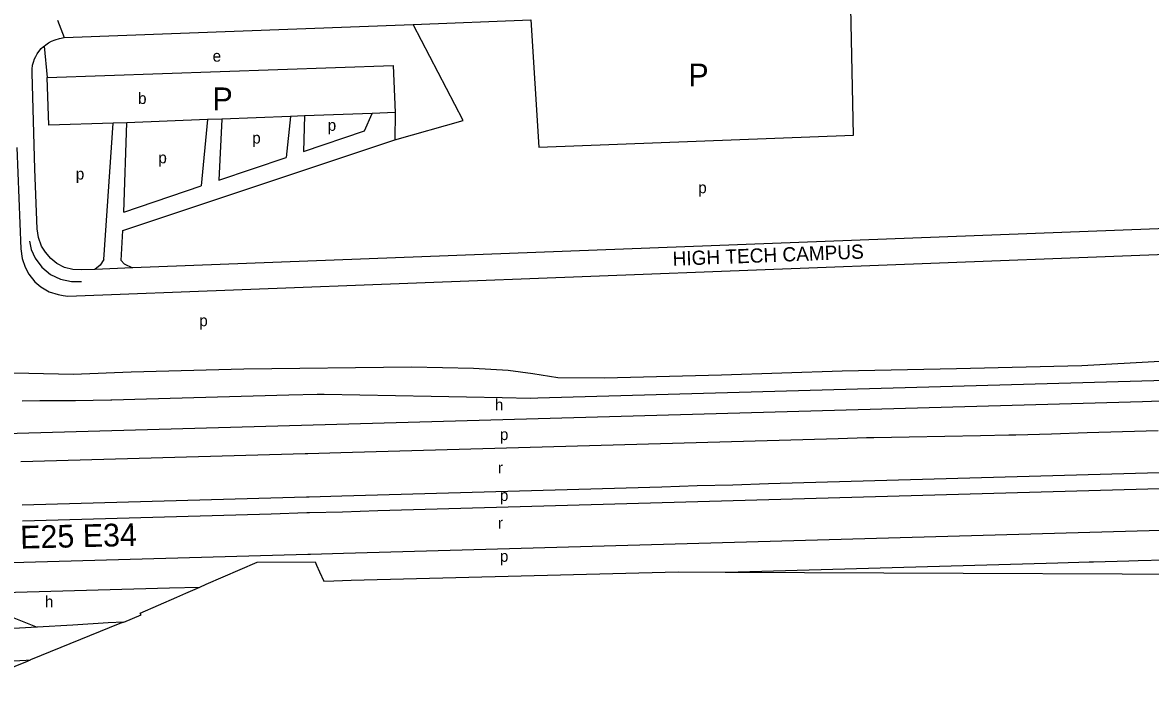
# Model space of a CAD drawing. Extents: x 158358 to 160383, y 379531 to 380764.
# Drawn here: x 159510.8 to 159907.3, y 379530.7 to 379764 of the extents above; entities that cross this region are included whole.
import ezdxf

# ---------------------------------------------------------------- set-up
doc = ezdxf.new("R2010")
doc.units = 0
for name, color, linetype in [('BLT_Basislijn', 7, 'Continuous'), ('BLT_Bebouwing', 7, 'Continuous'), ('BLT_Centroide', 7, 'Continuous'), ('BLT_Gemeentegrens', 7, 'Continuous'), ('BLT_Straatnaam', 7, 'Continuous'), ('BLT_Straatnaam_hoofdweg', 7, 'Continuous'), ('BLT_Tekst_parkeren', 7, 'Continuous'), ('BLT_Vlakafsluiter', 7, 'Continuous')]:
    doc.layers.add(name, color=color, linetype=linetype)

msp = doc.modelspace()

# ---------------------------------------------------------------- linework, layer by layer
at = {"layer": 'BLT_Basislijn'}
for p, q in [((159525.38, 379758.64), (159648.05, 379763.32)), ((159648.05, 379763.32), (159689.44, 379764.9)), ((159665.69, 379729.54), (159648.05, 379763.32)), ((159518.33, 379755.67), (159519.37, 379744.66)), ((159575.83, 379729.79), (159573.61, 379706.46)), ((159580.82, 379729.98), (159579.81, 379708.55)), ((159604.93, 379730.89), (159603.4, 379716.5)), ((159609.92, 379731.08), (159609.58, 379718.58)), ((159641.7, 379732.3), (159641.68, 379722.65)), ((159539.39, 379680.61), (159542.61, 379728.52)), ((159546.35, 379697.27), (159547.42, 379728.71)), ((159641.68, 379722.65), (159665.69, 379729.54)), ((159545.98, 379690.82), (159641.68, 379722.65)), ((159545.38, 379680.27), (159545.98, 379690.82)), ((159951.34, 379692.96), (159549.4, 379677.61))]:
    msp.add_line(p, q, dxfattribs=at)
for points in [[(159689.44, 379764.9), (159692.26, 379720.15), (159802.92, 379724.35), (159801.98, 379769.17)], [(159518.33, 379755.67), (159518.89, 379756.11), (159519.88, 379756.78), (159520.99, 379757.38), (159522.24, 379757.87), (159523.78, 379758.31), (159525.38, 379758.64)], [(159515.08, 379712.39), (159514.08, 379746.22), (159514.1, 379747.6), (159514.31, 379748.99), (159514.56, 379750), (159514.97, 379751.16), (159515.4, 379752.05), (159515.89, 379752.94), (159516.5, 379753.8), (159517.33, 379754.78), (159518.13, 379755.51), (159518.33, 379755.67)], [(159508.74, 379720.04), (159510.15, 379684.35), (159510.58, 379680.95), (159511.63, 379677.83), (159512.96, 379675.4), (159515.12, 379672.76), (159517.23, 379670.91), (159520.09, 379669.22), (159523.31, 379668.22), (159525, 379667.9), (159526.69, 379667.74), (160139.53, 379691.14), (160142.9, 379691.52), (160144.79, 379692.1), (160146.54, 379692.75), (160148.23, 379693.53), (160149.78, 379694.5), (160152.48, 379696.8), (160183.67, 379730.79)], [(159609.58, 379718.58), (159631, 379725.8), (159633.73, 379731.99)], [(159579.81, 379708.55), (159603.4, 379716.5)], [(159536.15, 379677.11), (159531.45, 379676.93), (159528.45, 379677.04), (159525.55, 379677.78), (159522.82, 379679.2), (159520.68, 379680.91), (159518.78, 379683.13), (159517.47, 379685.3), (159516.33, 379688.31), (159515.88, 379691.34), (159515.08, 379712.39)], [(159546.35, 379697.27), (159573.61, 379706.46)], [(159513.24, 379687.01), (159513.84, 379684.12), (159515.24, 379681.01), (159517.59, 379677.89), (159520.57, 379675.36), (159524.11, 379673.71), (159527.92, 379672.86), (159531.48, 379672.9)], [(159539.39, 379680.61), (159538.08, 379678.63), (159536.15, 379677.11)], [(159545.38, 379680.27), (159546.48, 379679.06), (159549.4, 379677.61)], [(159549.4, 379677.61), (159536.15, 379677.11)], [(159955.34, 379648.64), (159936.38, 379646.49), (159910.66, 379644.68), (159883.14, 379643.15), (159839.13, 379642.16), (159798.91, 379641.34), (159756.54, 379639.86), (159715.31, 379638.82), (159698.99, 379638.99), (159690.12, 379640.38), (159681.45, 379641.51), (159669.3, 379642.26), (159647.45, 379642.73), (159588.55, 379641.96), (159548.99, 379640.97), (159528.55, 379640.14), (159502.38, 379640.72)], [(159916.8, 379638.17), (159904.3, 379637.81), (159891.81, 379637.46), (159879.31, 379637.1), (159866.82, 379636.75), (159854.32, 379636.39), (159841.83, 379636.04), (159829.33, 379635.68), (159816.84, 379635.33), (159804.34, 379634.97), (159791.85, 379634.62), (159779.35, 379634.26), (159766.86, 379633.91), (159754.36, 379633.55), (159741.87, 379633.2), (159729.37, 379632.84), (159716.88, 379632.49), (159704.38, 379632.13), (159691.89, 379631.78), (159689.39, 379631.71), (159679.38, 379631.9), (159666.87, 379632.13), (159654.36, 379632.37), (159641.85, 379632.61), (159629.33, 379632.84), (159616.82, 379633.08), (159614.32, 379633.13), (159604.32, 379632.84), (159591.83, 379632.49), (159579.33, 379632.14), (159566.84, 379631.78), (159554.34, 379631.43), (159542.16, 379631.08), (159541.85, 379631.07), (159535.6, 379630.97), (159529.35, 379630.9), (159523.11, 379630.85), (159516.86, 379630.82), (159510.61, 379630.77)], [(159917, 379630.92), (159904.51, 379630.56), (159892.01, 379630.21), (159879.52, 379629.85), (159867.02, 379629.5), (159854.53, 379629.14), (159842.03, 379628.79), (159829.54, 379628.43), (159817.04, 379628.08), (159804.55, 379627.73), (159792.05, 379627.37), (159779.56, 379627.02), (159767.06, 379626.66), (159754.57, 379626.31), (159742.07, 379625.95), (159729.58, 379625.6), (159717.08, 379625.24), (159704.59, 379624.89), (159692.09, 379624.53), (159679.6, 379624.18), (159667.1, 379623.82), (159654.61, 379623.47), (159642.11, 379623.11), (159629.62, 379622.76), (159617.13, 379622.4), (159604.63, 379622.05), (159592.14, 379621.69), (159579.64, 379621.34), (159567.15, 379620.98), (159554.65, 379620.63), (159542.16, 379620.28), (159529.66, 379619.92), (159517.17, 379619.57), (159504.67, 379619.21)], [(159510.14, 379609.46), (159522.64, 379609.82), (159535.13, 379610.17), (159547.63, 379610.53), (159560.12, 379610.88), (159572.62, 379611.24), (159585.11, 379611.59), (159597.61, 379611.95), (159610.1, 379612.3), (159610.24, 379612.3), (159611.04, 379612.33), (159622.6, 379612.66), (159635.09, 379613.01), (159647.59, 379613.36), (159660.08, 379613.72), (159672.58, 379614.07), (159685.07, 379614.43), (159697.57, 379614.78), (159710.06, 379615.14), (159722.56, 379615.49), (159735.05, 379615.85), (159747.55, 379616.2), (159760.04, 379616.56), (159772.54, 379616.91), (159785.03, 379617.27), (159797.53, 379617.62), (159807.52, 379617.91), (159810.02, 379617.95), (159822.52, 379618.2), (159835.02, 379618.44), (159847.52, 379618.68), (159857.52, 379618.87), (159860.02, 379618.95), (159872.51, 379619.3), (159885.01, 379619.66), (159897.5, 379620.01), (159910, 379620.37)], [(159510.58, 379594.27), (159523.07, 379594.62), (159535.57, 379594.98), (159548.06, 379595.33), (159560.56, 379595.69), (159573.05, 379596.04), (159585.55, 379596.4), (159598.04, 379596.75), (159610.54, 379597.11), (159610.67, 379597.11), (159611.47, 379597.13), (159623.03, 379597.46), (159635.53, 379597.82), (159648.02, 379598.17), (159660.52, 379598.53), (159673.01, 379598.88), (159685.51, 379599.24), (159698, 379599.59), (159710.5, 379599.94), (159722.99, 379600.3), (159735.49, 379600.65), (159747.98, 379601.01), (159760.48, 379601.36), (159772.97, 379601.72), (159785.47, 379602.07), (159797.96, 379602.43), (159810.45, 379602.78), (159822.95, 379603.14), (159835.44, 379603.49), (159847.94, 379603.85), (159860.43, 379604.2), (159872.93, 379604.56), (159885.42, 379604.91), (159897.92, 379605.27), (159910.41, 379605.62)], [(159510.73, 379588.67), (159523.23, 379589.03), (159535.72, 379589.38), (159548.22, 379589.73), (159560.71, 379590.09), (159573.21, 379590.44), (159585.7, 379590.8), (159598.2, 379591.15), (159610.69, 379591.51), (159610.83, 379591.51), (159611.63, 379591.54), (159623.19, 379591.86), (159635.68, 379592.22), (159648.18, 379592.57), (159660.67, 379592.93), (159673.17, 379593.28), (159685.66, 379593.64), (159698.16, 379593.99), (159710.65, 379594.35), (159723.15, 379594.7), (159735.64, 379595.06), (159748.14, 379595.41), (159760.63, 379595.77), (159773.13, 379596.12), (159785.62, 379596.48), (159798.12, 379596.83), (159810.61, 379597.19), (159823.11, 379597.54), (159835.6, 379597.89), (159848.1, 379598.25), (159860.59, 379598.6), (159873.09, 379598.96), (159885.58, 379599.31), (159898.08, 379599.67), (159910.57, 379600.02)], [(159910.99, 379585.28), (159898.5, 379584.92), (159886, 379584.57), (159873.51, 379584.21), (159861.01, 379583.86), (159848.52, 379583.51), (159836.02, 379583.15), (159823.53, 379582.8), (159811.03, 379582.44), (159798.54, 379582.09), (159786.04, 379581.73), (159773.55, 379581.38), (159761.05, 379581.02), (159748.56, 379580.67), (159736.06, 379580.31), (159723.57, 379579.96), (159711.07, 379579.6), (159698.58, 379579.25), (159686.08, 379578.89), (159673.59, 379578.54), (159661.09, 379578.18), (159648.6, 379577.83), (159636.1, 379577.47), (159623.61, 379577.12), (159612.05, 379576.79), (159611.25, 379576.77), (159611.11, 379576.76), (159598.62, 379576.41), (159586.12, 379576.06), (159573.63, 379575.7), (159561.13, 379575.35), (159548.64, 379574.99), (159536.14, 379574.64), (159523.65, 379574.28), (159511.15, 379573.93), (159498.66, 379573.57)], [(159757.8, 379570.58), (159762.31, 379570.7), (159774.8, 379571.06), (159787.3, 379571.41), (159799.79, 379571.77), (159812.28, 379572.12), (159824.78, 379572.48), (159837.27, 379572.83), (159849.77, 379573.19), (159862.26, 379573.54), (159874.76, 379573.9), (159885.73, 379574.21), (159887.25, 379574.25), (159899.75, 379574.61), (159902.97, 379574.7), (159912.24, 379574.96)], [(159476.2, 379562.58), (159487.42, 379562.9), (159499.91, 379563.25), (159512.41, 379563.61), (159524.9, 379563.96), (159537.4, 379564.32), (159549.89, 379564.67), (159562.39, 379565.03), (159573.07, 379565.33)], [(159546.33, 379553.02), (159540.89, 379552.71), (159528.41, 379551.98), (159515.93, 379551.25)], [(159515.93, 379551.25), (159505.55, 379550.64), (159504.9, 379550.6), (159503.95, 379550.55), (159503.45, 379550.51), (159497.23, 379550.11), (159495.75, 379550), (159491.04, 379549.66), (159486.92, 379549.32), (159482.65, 379548.92)], [(159487.76, 379538.14), (159491.91, 379538.52), (159512.02, 379539.67), (159513.59, 379539.72)]]:
    msp.add_lwpolyline(points, dxfattribs=at)
at = {"layer": 'BLT_Bebouwing'}
msp.add_line((159641.7, 379732.3), (159633.73, 379731.99), dxfattribs=at)
for points in [[(159519.37, 379744.66), (159641.05, 379748.87), (159641.7, 379732.3)], [(159542.61, 379728.52), (159520, 379727.8), (159519.37, 379744.66)], [(159575.83, 379729.79), (159547.42, 379728.71)], [(159580.82, 379729.98), (159575.83, 379729.79)], [(159604.93, 379730.89), (159580.82, 379729.98)], [(159609.92, 379731.08), (159604.93, 379730.89)], [(159633.73, 379731.99), (159609.92, 379731.08)], [(159547.42, 379728.71), (159542.61, 379728.52)]]:
    msp.add_lwpolyline(points, dxfattribs=at)
at = {"layer": 'BLT_Gemeentegrens'}
for points in [[(159573.07, 379565.33), (159575.33, 379566.31), (159593.3, 379574.13), (159613.6, 379574.23), (159614.15, 379573.04), (159615.19, 379570.75), (159616.69, 379567.46), (159620.2, 379567.55), (159626.27, 379567.71), (159741.28, 379570.64), (159757.8, 379570.58)], [(159757.8, 379570.58), (159981, 379569.66)], [(159546.33, 379553.02), (159552.46, 379555.52), (159552.06, 379556.19), (159564.98, 379561.81), (159568.16, 379563.19), (159573.07, 379565.33)], [(159546.33, 379553.02), (159544.95, 379552.46), (159513.59, 379539.72)], [(159487.76, 379538.14), (159491.22, 379530.71), (159500, 379534.2), (159512.52, 379539.29), (159513.59, 379539.72)]]:
    msp.add_lwpolyline(points, dxfattribs=at)
at = {"layer": 'BLT_Vlakafsluiter'}
for p, q in [((159523.09, 379764.79), (159525.38, 379758.64)), ((159505.95, 379555.17), (159515.93, 379551.25))]:
    msp.add_line(p, q, dxfattribs=at)

# ---------------------------------------------------------------- texts
at = {"layer": 'BLT_Centroide'}
for s, p in [('e', (159577.59, 379750.19)), ('b', (159551.37, 379735.3)), ('p', (159618.05, 379725.85)), ('p', (159591.5, 379721.38)), ('p', (159558.51, 379714.43)), ('p', (159529.48, 379708.72)), ('p', (159748.3, 379703.9)), ('p', (159572.89, 379657.11)), ('h', (159676.8, 379627.5)), ('p', (159678.57, 379617.05)), ('r', (159677.85, 379605.33)), ('p', (159678.57, 379595.63)), ('r', (159677.85, 379585.88)), ('p', (159678.57, 379574.22)), ('h', (159518.62, 379558.21))]:
    msp.add_text(s, height=4, dxfattribs=at).set_placement(p)
at = {"layer": 'BLT_Straatnaam'}
msp.add_text('HIGH TECH CAMPUS', height=5, rotation=2.1866, dxfattribs=at).set_placement((159739.39, 379678.35))
at = {"layer": 'BLT_Straatnaam_hoofdweg'}
msp.add_text('A2 A67 E25 E34', height=8, rotation=1.3536, dxfattribs=at).set_placement((159471.96, 379577.96))
at = {"layer": 'BLT_Tekst_parkeren'}
for p in [(159744.84, 379741.49), (159577.52, 379733.1)]:
    msp.add_text('P', height=8, dxfattribs=at).set_placement(p)

doc.saveas('drawing.dxf')
